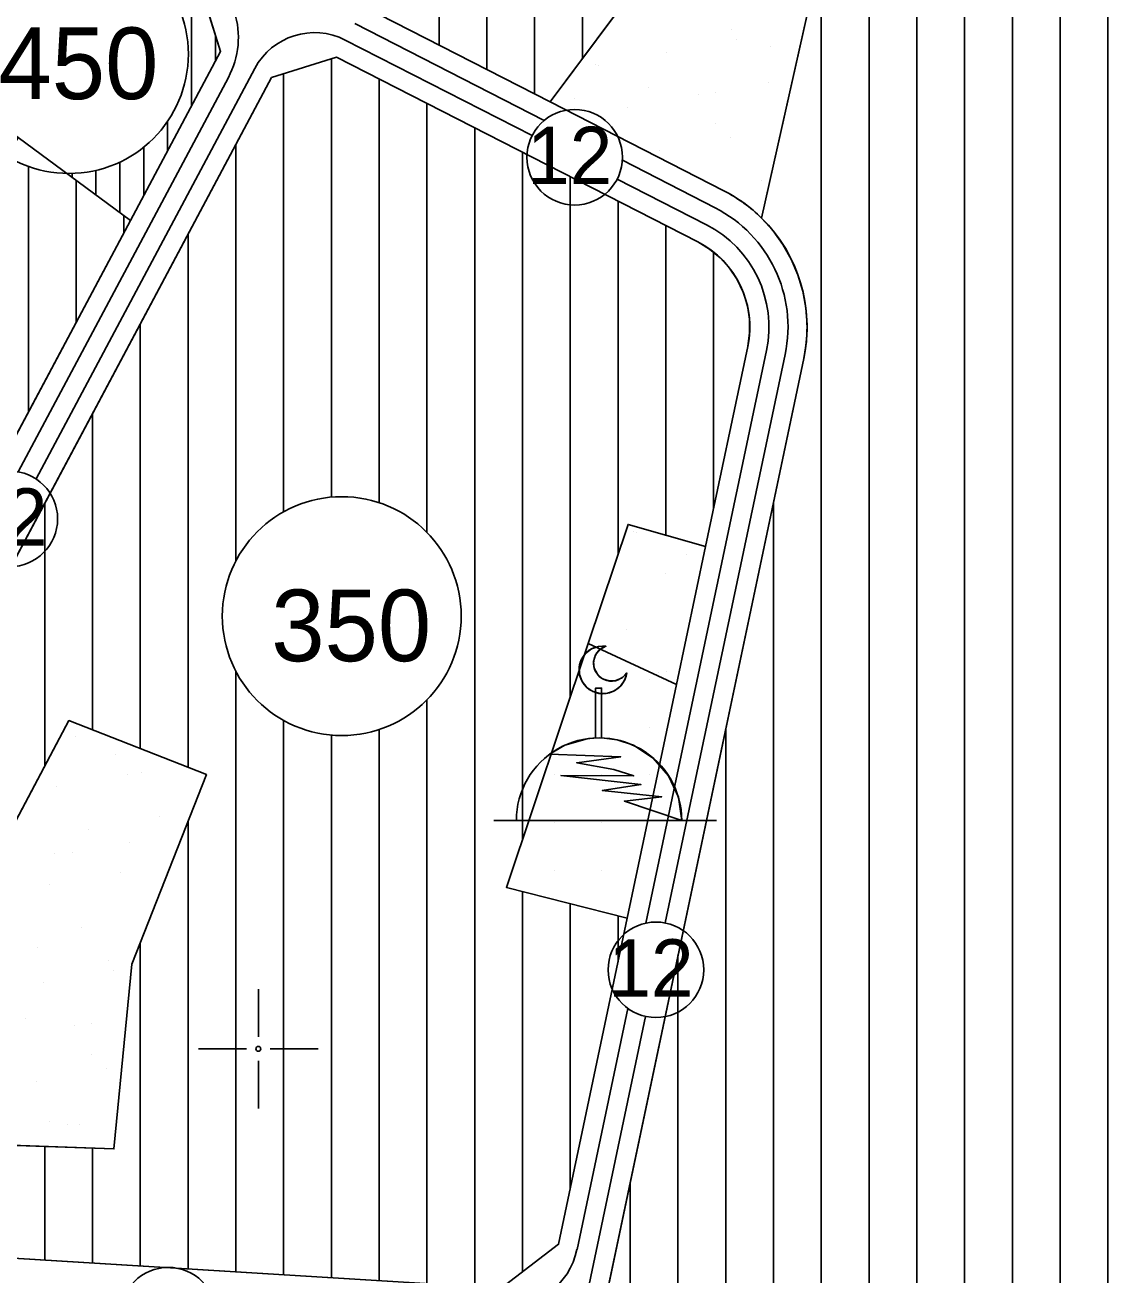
# Model space of a CAD drawing. Extents: x 419109 to 421295, y 4452223 to 4457798.
# Drawn here: x 420451.2 to 420677.8, y 4452952.7 to 4453214.3 of the extents above; entities that cross this region are included whole.
import ezdxf

# ---------------------------------------------------------------- set-up
doc = ezdxf.new("R2010")
doc.units = 0
for name, color, linetype in [('ADA', 7, 'Continuous'), ('ADAKENARI', 7, 'Continuous'), ('Default', 7, 'Continuous'), ('KALDIRIM', 7, 'Continuous'), ('KD_DAIRE', 7, 'Continuous'), ('KD_YGEN', 7, 'Continuous'), ('LJ_SEMBOL', 7, 'Continuous'), ('PAFTALAMA', 7, 'Continuous'), ('PL_AYA_PARK_DINLENME', 7, 'Continuous'), ('PL_KON_MEV_350', 7, 'Continuous'), ('PL_KON_MEV_450', 7, 'Continuous'), ('PL_SAY_DINI_TESIS', 7, 'Continuous'), ('SM_DAIRE', 7, 'Continuous'), ('SM_TAKS', 7, 'Continuous'), ('TR_DINITESIS', 7, 'Continuous'), ('TR_ORTAYOGUNKONUT', 7, 'Continuous'), ('TR_PARKALANI', 7, 'Continuous'), ('TR_YUKSEKYOGUNKONUT', 7, 'Continuous')]:
    doc.layers.add(name, color=color, linetype=linetype)

# ---------------------------------------------------------------- blocks, each defined once
blk = doc.blocks.new('POINT_DISPLAY')
at = {"layer": 'Default'}
blk.add_line((0, 0), (0, 0), dxfattribs=at)
blk = doc.blocks.new('CAMI_3')
at = {"layer": 'Default'}
blk.add_line((210.320774, -86.17823), (-256.287561, -86.19962), dxfattribs=at)
for points in [[(22.086155, 223.44137), (17.847466, 208.35529), (9.147302, 195.32211), (-3.159784, 185.622), (-17.864957, 180.20772), (-33.523837, 179.61109), (-48.598368, 183.89069), (-61.607891, 192.62618), (-71.274576, 204.95954), (-76.648937, 219.67935), (-77.203089, 235.33979), (-72.882603, 250.40265), (-64.111848, 263.38843), (-51.75231, 273.02162), (-37.017975, 278.35602), (-21.356088, 278.86768), (-33.888665, 271.92668), (-42.903796, 260.79248), (-47.085718, 247.09013), (-45.824076, 232.81948), (-39.303008, 220.06336), (-28.474268, 210.68352), (-14.918316, 206.04896), (-0.613652, 206.83609), (12.351951, 212.93003)], [(22.086155, 223.44137), (17.847466, 208.35529), (9.147302, 195.32211), (-3.159784, 185.622), (-17.864957, 180.20772), (-33.523837, 179.61109), (-48.598368, 183.89069), (-61.607891, 192.62618), (-71.274576, 204.95954), (-76.648937, 219.67935), (-77.203089, 235.33979), (-72.882603, 250.40265), (-64.111848, 263.38843), (-51.75231, 273.02162), (-37.017975, 278.35602), (-21.356088, 278.86768), (-33.888665, 271.92668), (-42.903796, 260.79248), (-47.085718, 247.09013), (-45.824076, 232.81948), (-39.303008, 220.06336), (-28.474268, 210.68352), (-14.918316, 206.04896), (-0.613652, 206.83609), (12.351951, 212.93003)], [(137.278869, -86.05749), (17.449309, -45.52793), (95.326764, -36.36587), (-29.015392, -23.27723), (51.84643, -10.68626), (-115.64944, 8.18652), (36.905483, 7.40015), (-4.801393, 20.56975), (-82.622085, 34.92295), (9.59612, 47.40147), (-139.308018, 52.62453), (-107.674786, 71.36467), (-60.411697, 85.24237), (-42.96472, 86.85478), (-42.96472, 191.03756), (-30.46472, 191.03756), (-30.46472, 86.92216), (1.9676, 82.83647), (36.109793, 71.36467), (77.548597, 44.73357), (109.805989, 7.50655), (130.268668, -37.30046)]]:
    blk.add_lwpolyline(points, close=True, dxfattribs=at)
for centre, radius, start, end in [((-27.574608, 229.25589), 50, 82.8556, 353.32194), ((-27.574608, 229.25589), 50, 82.8556, 353.32194), ((-9.788411, 243.19642), 37.5, 107.96713, 328.21041), ((-9.788411, 243.19642), 37.5, 107.96713, 328.21041), ((-35.782496, -86.05749), 173.0614, 359.96699, 180)]:
    blk.add_arc(centre, radius, start, end, dxfattribs=at)

msp = doc.modelspace()

# ---------------------------------------------------------------- linework, layer by layer
at = {"layer": 'ADA'}
for p, q in [((420561.07, 4453198.24), (420595.11, 4453243.91)), ((420618.24, 4453231.52), (420605.34, 4453173.91)), ((420449.71, 4453190.78), (420473.24, 4453173.42)), ((420577.4, 4453109.8), (420569.04, 4453084.88)), ((420593.61, 4453105.17), (420577.4, 4453109.8)), ((420569.04, 4453084.88), (420551.91, 4453033.81)), ((420569.04, 4453084.88), (420587.52, 4453076.25)), ((420460.34, 4453068.74), (420431.07, 4453013.51)), ((420489.13, 4453057.41), (420460.34, 4453068.74)), ((420473.55, 4453017.76), (420489.13, 4453057.41)), ((420551.91, 4453033.81), (420577.22, 4453027.36)), ((420469.78, 4452979.05), (420473.55, 4453017.76)), ((420430.6, 4452980.47), (420469.78, 4452979.05))]:
    msp.add_line(p, q, dxfattribs=at)
at = {"layer": 'ADAKENARI'}
for p, q in [((420487.9, 4453222.19), (420492.1, 4453208.81)), ((420561.07, 4453198.24), (420522.03, 4453218.21)), ((420492.1, 4453208.81), (420473.24, 4453173.42)), ((420502.78, 4453203.35), (420516.39, 4453207.62)), ((420516.39, 4453207.62), (420591.97, 4453168.95)), ((420419.19, 4453046.47), (420502.78, 4453203.35)), ((420597.44, 4453179.63), (420561.07, 4453198.24)), ((420473.24, 4453173.42), (420408.6, 4453052.12)), ((420602.43, 4453147.02), (420593.61, 4453105.17)), ((420572.37, 4452946.15), (420614.17, 4453144.54)), ((420593.61, 4453105.17), (420587.52, 4453076.25)), ((420587.52, 4453076.25), (420577.22, 4453027.36)), ((420577.22, 4453027.36), (420562.83, 4452959.08)), ((420550.79, 4452949.9), (420414.63, 4452958.26)), ((420562.83, 4452959.08), (420550.79, 4452949.9))]:
    msp.add_line(p, q, dxfattribs=at)
for radius, start, end in [(32, 45.3685, 62.905), (32, 348.1023, 45.3685), (20, 348.1023, 62.905)]:
    msp.add_arc((420582.86, 4453151.14), radius, start, end, dxfattribs=at)
at = {"layer": 'KALDIRIM'}
for p, q in [((420559.85, 4453194.36), (420520.23, 4453214.64)), ((420557.3, 4453191.18), (420518.19, 4453211.19)), ((420499.26, 4453205.24), (420453.47, 4453119.32)), ((420493.73, 4453203.36), (420449.73, 4453120.8)), ((420595.61, 4453176.07), (420576.19, 4453186.01)), ((420593.79, 4453172.51), (420575.1, 4453182.07)), ((420581.09, 4453026.32), (420606.35, 4453146.19)), ((420585.18, 4453026.35), (420610.26, 4453145.37)), ((420566.7, 4452958.02), (420577.33, 4453008.47)), ((420557.75, 4452896.15), (420581.06, 4453006.78))]:
    msp.add_line(p, q, dxfattribs=at)
for centre, radius, start, end in [((420478.01, 4453211.74), 17.81, 331.9477, 62.905), ((420511.75, 4453198.59), 14.15, 62.905, 151.9477), ((420582.86, 4453151.14), 28, 348.1023, 62.905), ((420582.86, 4453151.14), 24, 348.1023, 62.905), ((420551.72, 4452961.17), 15.3, 266.4895, 348.1023)]:
    msp.add_arc(centre, radius, start, end, dxfattribs=at)
at = {"layer": 'KD_DAIRE'}
for centre in [(420566.21, 4453186.65), (420447.99, 4453110.95), (420583.22, 4453016.55), (420481.16, 4452944.25)]:
    msp.add_circle(centre, 10, dxfattribs=at)
at = {"layer": 'PAFTALAMA'}
for p, q in [((420500, 4453002.5), (420500, 4453012.5)), ((420487.5, 4453000), (420497.5, 4453000)), ((420502.5, 4453000), (420512.5, 4453000)), ((420500, 4452997.5), (420500, 4452987.5))]:
    msp.add_line(p, q, dxfattribs=at)
msp.add_circle((420500, 4453000), 0.5, dxfattribs=at)
at = {"layer": 'PL_AYA_PARK_DINLENME'}
for points in [[(420618.24, 4453231.52), (420605.34, 4453173.91), (420604.46, 4453174.76), (420603.54, 4453175.57), (420602.59, 4453176.34), (420601.61, 4453177.08), (420600.6, 4453177.77), (420599.57, 4453178.43), (420598.52, 4453179.05), (420597.44, 4453179.63), (420561.07, 4453198.24), (420595.11, 4453243.91)], [(420577.4, 4453109.8), (420593.61, 4453105.17), (420587.52, 4453076.25), (420569.04, 4453084.88)], [(420431.07, 4453013.51), (420460.34, 4453068.74), (420489.13, 4453057.41), (420473.55, 4453017.76), (420469.78, 4452979.05), (420430.6, 4452980.47)]]:
    msp.add_lwpolyline(points, close=True, dxfattribs=at)
at = {"layer": 'PL_KON_MEV_350'}
for points in [[(420595.11, 4453243.91), (420561.07, 4453198.24), (420522.03, 4453218.21)], [(420572.37, 4452946.15), (420614.17, 4453144.54), (420614.71, 4453148.06), (420614.86, 4453151.6), (420614.61, 4453155.15), (420613.97, 4453158.64), (420612.95, 4453162.04), (420611.55, 4453165.31), (420609.81, 4453168.4), (420607.73, 4453171.28), (420605.34, 4453173.91), (420618.24, 4453231.52)], [(420419.19, 4453046.47), (420502.78, 4453203.35), (420516.39, 4453207.62), (420591.97, 4453168.95), (420594.45, 4453167.44), (420596.68, 4453165.6), (420598.63, 4453163.45), (420600.24, 4453161.04), (420601.49, 4453158.42), (420602.35, 4453155.65), (420602.79, 4453152.79), (420602.82, 4453149.89), (420602.43, 4453147.02), (420593.61, 4453105.17), (420577.4, 4453109.8), (420569.04, 4453084.88), (420551.91, 4453033.81), (420577.22, 4453027.36), (420562.83, 4452959.08), (420550.79, 4452949.9), (420414.63, 4452958.26)], [(420430.6, 4452980.47), (420469.78, 4452979.05), (420473.55, 4453017.76), (420489.13, 4453057.41), (420460.34, 4453068.74), (420431.07, 4453013.51)]]:
    msp.add_lwpolyline(points, dxfattribs=at)
msp.add_lwpolyline([(420345.71, 4452985.56), (420346.19, 4453017.19), (420363.18, 4453066.76), (420380.65, 4453058.73), (420434.4, 4453163.75), (420449.71, 4453190.78), (420473.24, 4453173.42), (420408.6, 4453052.12), (420405.94, 4453046.78), (420403.56, 4453041.31), (420401.48, 4453035.72), (420399.7, 4453030.03), (420398.22, 4453024.25), (420397.06, 4453018.41), (420396.2, 4453012.5), (420395.67, 4453006.57), (420393.31, 4452969.58), (420382.69, 4452960.21), (420311.22, 4452964.6), (420301.86, 4452975.19), (420302.65, 4452988.12)], close=True, dxfattribs=at)
at = {"layer": 'PL_KON_MEV_450'}
msp.add_lwpolyline([(420449.71, 4453190.78), (420426.02, 4453207.78), (420446.14, 4453232.57), (420461.35, 4453235.77), (420487.9, 4453222.19), (420492.1, 4453208.81), (420473.24, 4453173.42)], close=True, dxfattribs=at)
at = {"layer": 'PL_SAY_DINI_TESIS'}
msp.add_lwpolyline([(420587.52, 4453076.25), (420577.22, 4453027.36), (420551.91, 4453033.81), (420569.04, 4453084.88)], close=True, dxfattribs=at)
at = {"layer": 'SM_DAIRE'}
for centre in [(420460.35, 4453208.26), (420517.46, 4453090.59)]:
    msp.add_circle(centre, 25, dxfattribs=at)
at = {"layer": 'TR_ORTAYOGUNKONUT'}
for p, q in [((420677.83, 4452922.9), (420677.83, 4453358.21)), ((420567.83, 4453207.31), (420567.83, 4453325.42)), ((420557.83, 4453199.89), (420557.83, 4453306.65)), ((420547.83, 4453205.01), (420547.83, 4453287.89)), ((420627.83, 4452934.95), (420627.83, 4453275.8)), ((420537.83, 4453210.12), (420537.83, 4453269.12)), ((420667.83, 4452925.1), (420667.83, 4453263.99)), ((420637.83, 4452931.72), (420637.83, 4453262.35)), ((420657.83, 4452927.31), (420657.83, 4453258.88)), ((420647.83, 4452929.51), (420647.83, 4453258.43)), ((420617.83, 4452936.13), (420617.83, 4453229.7)), ((420515.29, 4453115.5), (420515.29, 4453207.27)), ((420505.29, 4453112.43), (420505.29, 4453204.13)), ((420525.29, 4453114.34), (420525.29, 4453203.06)), ((420535.29, 4453108.11), (420535.29, 4453197.95)), ((420545.29, 4452950.24), (420545.29, 4453192.83)), ((420495.29, 4453102.16), (420495.29, 4453189.28)), ((420555.29, 4453043.88), (420555.29, 4453187.71)), ((420451.86, 4453133.29), (420451.86, 4453184.75)), ((420461.86, 4453152.06), (420461.86, 4453181.82)), ((420565.29, 4453073.7), (420565.29, 4453182.6)), ((420575.29, 4453103.51), (420575.29, 4453177.48)), ((420471.86, 4453170.82), (420471.86, 4453174.44)), ((420585.29, 4453107.55), (420585.29, 4453172.37)), ((420485.29, 4453058.92), (420485.29, 4453170.51)), ((420595.29, 4453113.11), (420595.29, 4453166.75)), ((420475.29, 4453062.86), (420475.29, 4453151.75)), ((420465.29, 4453066.79), (420465.29, 4453132.98)), ((420455.29, 4453059.21), (420455.29, 4453114.22)), ((420607.83, 4452938.33), (420607.83, 4453114.45)), ((420495.29, 4452953.31), (420495.29, 4453079.03)), ((420535.29, 4452950.85), (420535.29, 4453073.07)), ((420505.29, 4452952.69), (420505.29, 4453068.75)), ((420515.29, 4452952.08), (420515.29, 4453065.69)), ((420525.29, 4452951.47), (420525.29, 4453066.85)), ((420597.83, 4452940.54), (420597.83, 4453066.99)), ((420485.29, 4452953.92), (420485.29, 4453047.63)), ((420555.29, 4452953.33), (420555.29, 4453032.95)), ((420565.29, 4452970.73), (420565.29, 4453030.4)), ((420575.29, 4453018.19), (420575.29, 4453027.85)), ((420475.29, 4452954.53), (420475.29, 4453022.17)), ((420587.83, 4452942.74), (420587.83, 4453019.52)), ((420455.29, 4452955.76), (420455.29, 4452979.58)), ((420465.29, 4452955.15), (420465.29, 4452979.22)), ((420577.83, 4452944.94), (420577.83, 4452972.06))]:
    msp.add_line(p, q, dxfattribs=at)
at = {"layer": 'TR_YUKSEKYOGUNKONUT'}
for p, q in [((420486.02, 4453197.4), (420486.02, 4453223.16)), ((420491.02, 4453206.78), (420491.02, 4453212.26)), ((420481.02, 4453188.01), (420481.02, 4453194.19)), ((420476.02, 4453178.63), (420476.02, 4453188.78)), ((420471.02, 4453175.06), (420471.02, 4453185.65)), ((420461.02, 4453182.44), (420461.02, 4453183.27)), ((420466.02, 4453178.75), (420466.02, 4453183.91))]:
    msp.add_line(p, q, dxfattribs=at)

# ---------------------------------------------------------------- block references
at = {"layer": 'LJ_SEMBOL', "xscale": 0.1, "yscale": 0.10000000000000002}
msp.add_blockref('CAMI_3', (420574.89, 4453056.41), dxfattribs=at)
at = {"layer": 'TR_DINITESIS', "xscale": 0.1, "yscale": 0.10000000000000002}
for p in [(420589.04, 4453106.25), (420571.91, 4453077.36), (420581.91, 4453077.36), (420571.91, 4453067.36), (420581.91, 4453067.36), (420561.91, 4453057.36), (420571.91, 4453057.36), (420581.91, 4453057.36), (420561.91, 4453047.36), (420571.91, 4453047.36), (420561.91, 4453037.36), (420571.91, 4453037.36)]:
    msp.add_blockref('POINT_DISPLAY', p, dxfattribs=at)
at = {"layer": 'TR_PARKALANI', "xscale": 0.1, "yscale": 0.10000000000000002}
for p in [(420599.09, 4453213.4), (420600.18, 4453211.27), (420607.11, 4453209.75), (420585.41, 4453208.67), (420570.63, 4453206.06), (420571.27, 4453205.79), (420581.71, 4453201.23), (420606.84, 4453202.29), (420566.07, 4453198.91), (420592.07, 4453199.69), (420595.62, 4453200.11), (420577.29, 4453197.08), (420595.62, 4453193.71), (420598.73, 4453190.71), (420583.95, 4453188.1), (420605.39, 4453181.73), (420578.6, 4453108.4), (420579.24, 4453108.13), (420589.68, 4453103.57), (420585.26, 4453099.42), (420577.15, 4453087.84), (420583.81, 4453078.86), (420585.34, 4453078.95), (420461.66, 4453065.46), (420465.95, 4453066.52), (420470.08, 4453061.6), (420472.61, 4453057.54), (420475.56, 4453057.93), (420457.84, 4453054.94), (420479.27, 4453048.56), (420464.5, 4453045.96), (420472.96, 4453043.16), (420457.32, 4453040.84), (420461.19, 4453041.09), (420471.16, 4453036.98), (420456.39, 4453034.37), (420463.05, 4453025.39), (420453.85, 4453021.15), (420468.62, 4453018.54), (420469.71, 4453016.41), (420454.94, 4453013.81), (420451.24, 4453006.37), (420461.6, 4453004.83), (420465.15, 4453005.25), (420465.15, 4452998.85), (420468.26, 4452995.85), (420453.48, 4452993.24), (420456.25, 4452984.73), (420460.15, 4452984.26), (420462.54, 4452984.07)]:
    msp.add_blockref('POINT_DISPLAY', p, dxfattribs=at)

# ---------------------------------------------------------------- texts
at = {"layer": 'KD_YGEN'}
for p in [(420556.24, 4453181.03), (420438.02, 4453105.34), (420573.25, 4453010.93)]:
    msp.add_text('12', height=12, dxfattribs=at).set_placement(p)
at = {"layer": 'SM_TAKS'}
for s, p in [('450', (420445.61, 4453198.82)), ('350', (420502.71, 4453081.15))]:
    msp.add_text(s, height=15, dxfattribs=at).set_placement(p)

doc.saveas('drawing.dxf')
